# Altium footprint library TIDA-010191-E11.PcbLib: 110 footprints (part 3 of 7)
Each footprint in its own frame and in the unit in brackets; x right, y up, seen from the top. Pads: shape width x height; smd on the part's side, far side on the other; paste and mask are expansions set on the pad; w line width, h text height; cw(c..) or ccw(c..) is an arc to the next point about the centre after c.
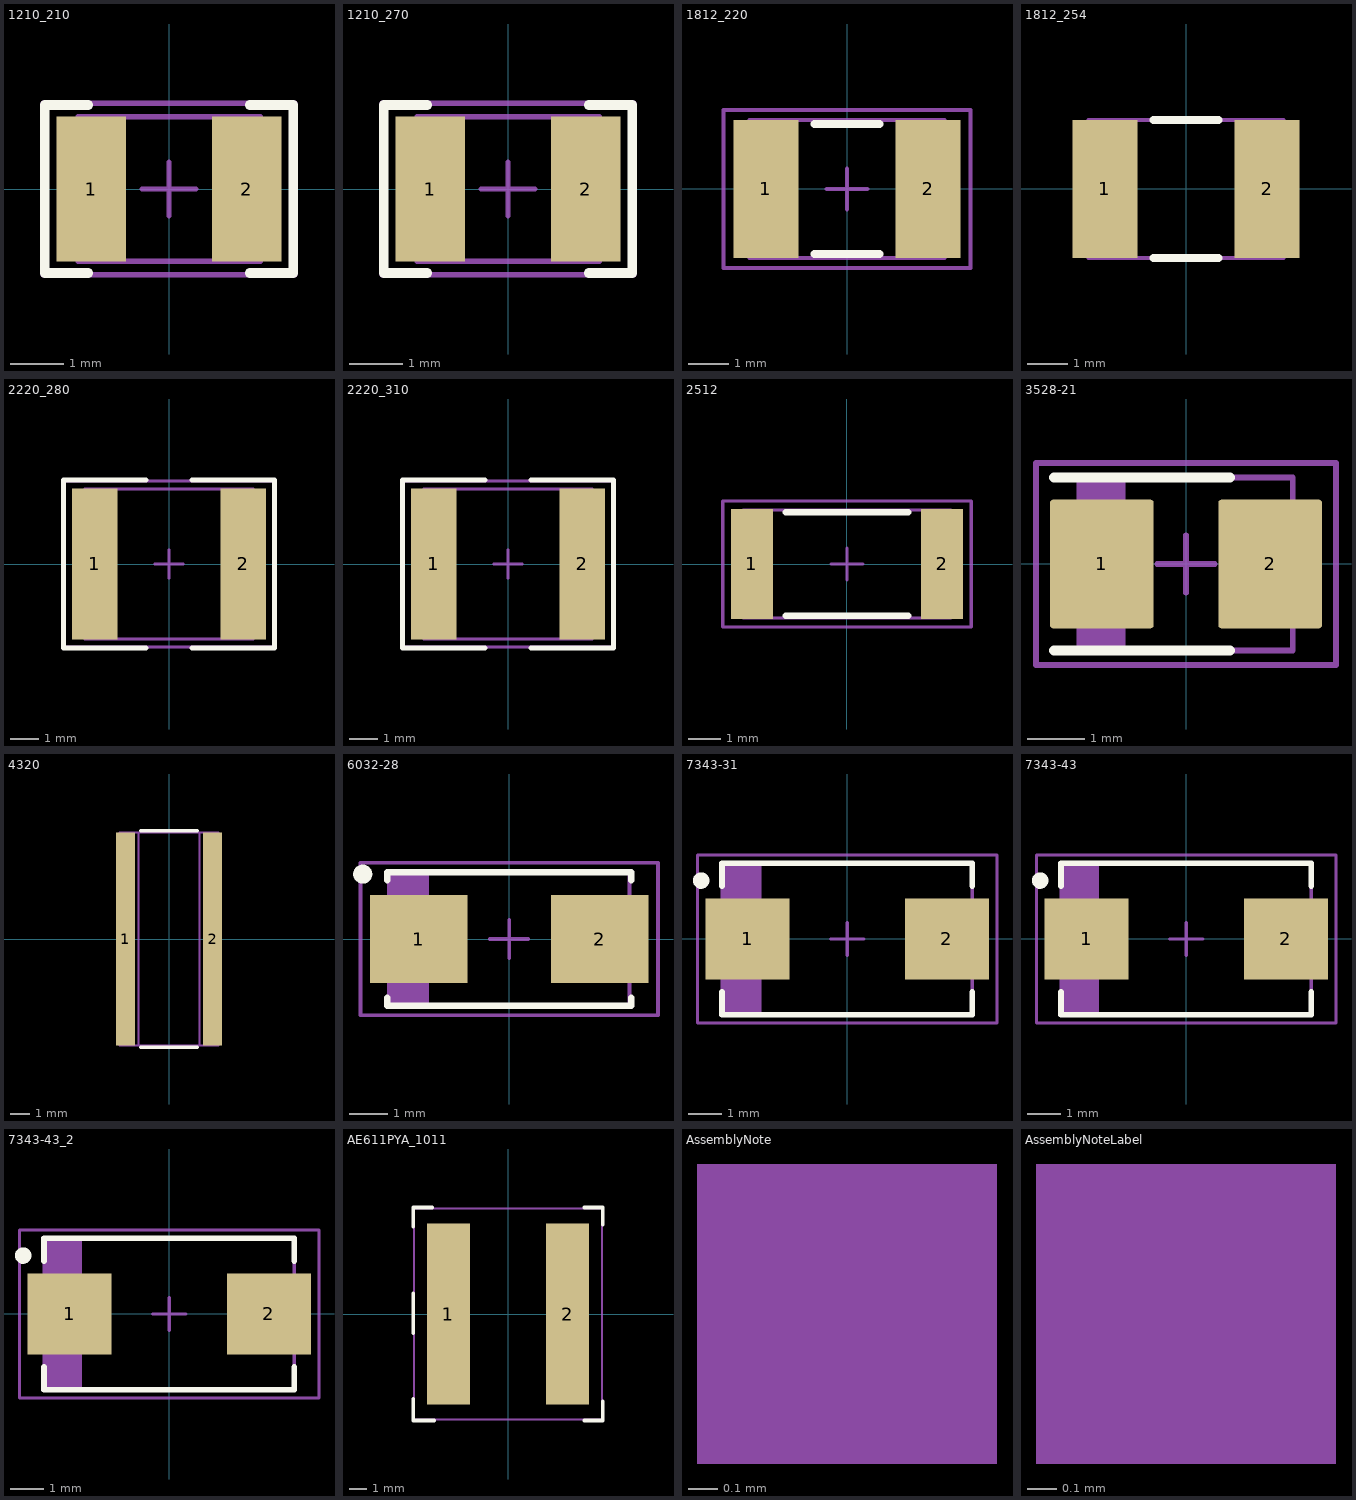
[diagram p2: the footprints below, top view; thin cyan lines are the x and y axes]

## 1210_210 [mm] "1210"
height 2.1
pads (2):
  rect 1.3x2.7 smd: 1(-1.45,0) 2(1.45,0)
Top Overlay:
  lines w0.178: -1.511,-1.568 -2.316,-1.568 -2.316,1.568 -1.511,1.568 ; 1.511,-1.568 2.316,-1.568 2.316,1.568 1.511,1.568
Mechanical 5:
  lines w0.1: -1.7,-1.35 -1.7,1.35 1.7,1.35 1.7,-1.35 -1.7,-1.35
  text ".Designator" at -1.4,-0.375 h0.76
Mechanical 13:
  lines w0.1: -1.2,-1.35 -1.2,1.35 ; 1.2,-1.35 1.2,1.35 ; -1.7,-1.35 1.7,-1.35 1.7,1.35 -1.7,1.35 -1.7,-1.35
Mechanical 15:
  lines w0.1: -0.5,0 0.5,0 ; 0,-0.5 0,0.5 ; -2.35,-1.6 2.35,-1.6 2.35,1.6 -2.35,1.6 -2.35,-1.6
3D body: height 2.1, standoff 0, extent 1.201,-1.349 1.699,1.349
3D body: height 2.1, standoff 0, extent -1.199,-1.349 1.199,1.349
3D body: height 2.1, standoff 0, extent -1.699,-1.349 -1.201,1.349

## 1210_270 [mm] "1210"
height 2.7
pads (2):
  rect 1.3x2.7 smd: 1(-1.45,0) 2(1.45,0)
Top Overlay:
  lines w0.178: -1.511,-1.568 -2.316,-1.568 -2.316,1.568 -1.511,1.568 ; 1.511,-1.568 2.316,-1.568 2.316,1.568 1.511,1.568
Mechanical 5:
  lines w0.1: -1.7,-1.35 1.7,-1.35 1.7,1.35 -1.7,1.35 -1.7,-1.35
  text ".Designator" at -1.4,-0.375 h0.76
Mechanical 13:
  lines w0.1: -1.2,-1.35 -1.2,1.35 ; 1.2,-1.35 1.2,1.35 ; -1.7,-1.35 -1.7,1.35 1.7,1.35 1.7,-1.35 -1.7,-1.35
Mechanical 15:
  lines w0.1: -0.5,0 0.5,0 ; 0,-0.5 0,0.5 ; -2.35,-1.6 -2.35,1.6 2.35,1.6 2.35,-1.6 -2.35,-1.6
3D body: height 2.7, standoff 0, extent -1.699,-1.349 -1.201,1.349
3D body: height 2.7, standoff 0, extent -1.199,-1.349 1.199,1.349
3D body: height 2.7, standoff 0, extent 1.201,-1.349 1.699,1.349

## 1812_220 [mm] "1812"
height 2.2
pads (2):
  rect 1.6x3.4 smd: 1(-2,0) 2(2,0)
Top Overlay:
  lines w0.2: -0.8,-1.6 0.8,-1.6 ; -0.8,1.6 0.8,1.6
Mechanical 5:
  lines w0.1: -2.4,-1.7 -2.4,1.7 2.4,1.7 2.4,-1.7 -2.4,-1.7
  text ".Designator" at -1.875,-0.5 h1.02
Mechanical 13:
  lines w0.1: -1.9,-1.7 -1.9,1.7 ; 1.9,-1.7 1.9,1.7 ; -2.4,-1.7 2.4,-1.7 2.4,1.7 -2.4,1.7 -2.4,-1.7
Mechanical 15:
  lines w0.1: -0.5,0 0.5,0 ; 0,-0.5 0,0.5 ; -3.05,-1.95 3.05,-1.95 3.05,1.95 -3.05,1.95 -3.05,-1.95
3D body: height 2.2, standoff 0, extent 1.901,-1.699 2.399,1.699
3D body: height 2.2, standoff 0, extent -1.899,-1.699 1.899,1.699
3D body: height 2.2, standoff 0, extent -2.399,-1.699 -1.901,1.699

## 1812_254 [mm] "SMD, 2-Leads, Body 4.8x3.4mm"
height 2.54
pads (2):
  rect 1.6x3.4 smd: 1(-2,0) 2(2,0)
Top Overlay:
  lines w0.2: -0.8,-1.7 0.8,-1.7 ; -0.8,1.7 0.8,1.7
Mechanical 5:
  lines w0.1: -1.9,-1.7 -1.9,1.7 ; 1.9,-1.7 1.9,1.7 ; -2.4,-1.7 2.4,-1.7 2.4,1.7 -2.4,1.7 -2.4,-1.7
  text ".Designator" at -1.875,-0.5 h1.02
3D body: height 2.54, standoff 0, extent -2.399,-1.699 -1.901,1.699
3D body: height 2.54, standoff 0, extent -1.899,-1.699 1.899,1.699
3D body: height 2.54, standoff 0, extent 1.901,-1.699 2.399,1.699

## 2220_280 [mm] "Chip Capacitor, Body 5.7x5.0mm, IPC Medium Density"
height 2.8
pads (2):
  rect 1.6x5.3 smd: 1(-2.6,0) 2(2.6,0)
Top Overlay:
  lines w0.178: -0.811,-2.939 -3.693,-2.939 -3.693,2.939 -0.811,2.939 ; 0.811,-2.939 3.693,-2.939 3.693,2.939 0.811,2.939
Mechanical 5:
  lines w0.1: -2.95,-2.625 -2.95,2.625 2.95,2.625 2.95,-2.625 -2.95,-2.625
  text ".Designator" at -1.875,-0.5 h1.02
Mechanical 13:
  lines w0.1: -2.75,-2.625 -2.75,2.625 ; 2.75,-2.625 2.75,2.625 ; -2.95,-2.625 2.95,-2.625 2.95,2.625 -2.95,2.625 -2.95,-2.625
Mechanical 15:
  lines w0.1: -0.5,0 0.5,0 ; 0,-0.5 0,0.5 ; -3.65,-2.9 3.65,-2.9 3.65,2.9 -3.65,2.9 -3.65,-2.9
3D body: height 2.8, standoff 0, extent 2.751,-2.624 2.949,2.624
3D body: height 2.8, standoff 0, extent -2.749,-2.624 2.749,2.624
3D body: height 2.8, standoff 0, extent -2.949,-2.624 -2.751,2.624

## 2220_310 [mm] "2220"
height 3.1
pads (2):
  rect 1.6x5.3 smd: 1(-2.6,0) 2(2.6,0)
Top Overlay:
  lines w0.178: -0.811,-2.939 -3.693,-2.939 -3.693,2.939 -0.811,2.939 ; 0.811,-2.939 3.693,-2.939 3.693,2.939 0.811,2.939
Mechanical 5:
  lines w0.1: -2.95,-2.625 -2.95,2.625 2.95,2.625 2.95,-2.625 -2.95,-2.625
  text ".Designator" at -1.875,-0.5 h1.02
Mechanical 13:
  lines w0.1: -2.75,-2.625 -2.75,2.625 ; 2.75,-2.625 2.75,2.625 ; -2.95,-2.625 2.95,-2.625 2.95,2.625 -2.95,2.625 -2.95,-2.625
Mechanical 15:
  lines w0.1: -0.5,0 0.5,0 ; 0,-0.5 0,0.5 ; -3.65,-2.9 3.65,-2.9 3.65,2.9 -3.65,2.9 -3.65,-2.9
3D body: height 3.1, standoff 0, extent 2.751,-2.624 2.949,2.624
3D body: height 3.1, standoff 0, extent -2.749,-2.624 2.749,2.624
3D body: height 3.1, standoff 0, extent -2.949,-2.624 -2.751,2.624

## 2512 [mm] "Chip Resistor, Body 6.3x3.2mm, IPC Medium Density"
height 0.71
pads (2):
  rect 1.3x3.4 smd: 1(-2.95,0) 2(2.95,0)
Top Overlay:
  lines w0.2: -1.9,-1.6 1.9,-1.6 ; -1.9,1.6 1.9,1.6
Mechanical 5:
  lines w0.1: -3.225,-1.675 3.225,-1.675 3.225,1.675 -3.225,1.675 -3.225,-1.675
  text ".Designator" at -1.85,-0.5 h1.02
Mechanical 13:
  lines w0.1: -2.463,-1.675 -2.463,1.675 ; 2.463,-1.675 2.463,1.675 ; -3.225,-1.675 3.225,-1.675 3.225,1.675 -3.225,1.675 -3.225,-1.675
Mechanical 15:
  lines w0.1: -0.5,0 0.5,0 ; 0,-0.5 0,0.5 ; -3.85,-1.95 3.85,-1.95 3.85,1.95 -3.85,1.95 -3.85,-1.95
3D body: height 0.71, standoff 0, extent -3.224,-1.674 -2.464,1.674
3D body: height 0.71, standoff 0, extent -2.462,-1.674 2.462,1.674
3D body: height 0.71, standoff 0, extent 2.464,-1.674 3.224,1.674

## 3528-21 [mm] "Medium Density IPC, based on Kemet datasheet 2016-10-20"
height 2.1
pads (2):
  rrect6% 1.8x2.23 smd: 1(-1.46,0) 2(1.46,0)
Top Overlay:
  lines w0.178: -2.286,-1.5 0.762,-1.5 ; -2.286,1.5 0.762,1.5
Mechanical 5:
  rectangle: -1.85,-1.5 -1.1,1.5
  lines w0.1: -1.1,-1.5 -1.1,1.5 ; -1.85,-1.5 1.85,-1.5 1.85,1.5 -1.85,1.5 -1.85,-1.5
  text ".Designator" at -0.9,-0.4 h1.2
Mechanical 15:
  lines w0.1: -0.5,0 0.5,0 ; 0,-0.5 0,0.5 ; -2.6,-1.75 -2.6,1.75 2.6,1.75 2.6,-1.75 -2.6,-1.75
3D body "3528-21.stp": height 2.12, standoff 0.01, extent -1.85,-1.5 1.85,1.5

## 4320 [mm] "SUSUMU"
height 0.7
pads (2):
  rect 1x11.2 smd: 1(-2.3,0) 2(2.3,0)
Top Overlay:
  lines w0.18: -1.5,-5.7 1.5,-5.7 ; -1.5,5.7 1.5,5.7
Mechanical 5:
  lines w0.1: -1.6,-5.6 -1.6,5.6 ; 1.6,-5.6 1.6,5.6 ; -2.6,-5.6 -2.6,5.6 2.6,5.6 2.6,-5.6 -2.6,-5.6
  text ".Designator" at 0.5,-1.9 h1.02
3D body: height 0.7, standoff 0, extent -1.599,-5.599 1.599,5.599
3D body: height 0.7, standoff 0, extent 1.601,-5.599 2.599,5.599
3D body: height 0.7, standoff 0, extent -2.599,-5.599 -1.601,5.599

## 6032-28 [mm] "Medium Density IPC based on Vishay Sprague 293D datasheet."
height 2.8
pads (2):
  rect 2.55x2.3 smd: 1(-2.375,0) 2(2.375,0)
Top Overlay:
  circle w0.25: c-3.839,1.7 r0.125
  lines w0.178: -3.2,-1.539 -3.2,-1.75 3.2,-1.75 3.2,-1.539 ; -3.2,1.539 -3.2,1.75 3.2,1.75 3.2,1.539
Mechanical 5:
  rectangle: -3.15,-1.75 -2.15,1.75
  lines w0.1: -2.15,-1.75 -2.15,1.75 ; -3.15,-1.75 3.15,-1.75 3.15,1.75 -3.15,1.75 -3.15,-1.75
  text ".Designator" at -1.85,-0.525 h1.02
Mechanical 15:
  lines w0.1: -0.5,0 0.5,0 ; 0,-0.5 0,0.5 ; -3.9,-2 -3.9,2 3.9,2 3.9,-2 -3.9,-2
3D body: height 2.8, standoff 2.8, extent -3.149,-1.749 -2.151,1.749
3D body: height 2.8, standoff 0, extent -3.15,-1.75 3.15,1.75

## 7343-31 [mm] "Medium Density based on Kemet T495 dimensions"
height 3.1
pads (2):
  rect 2.55x2.45 smd: 1(-3.025,0) 2(3.025,0)
Top Overlay:
  circle w0.25: c-4.439,1.775 r0.125
  lines w0.178: -3.8,-1.614 -3.8,-2.3 3.8,-2.3 3.8,-1.614 ; -3.8,1.614 -3.8,2.3 3.8,2.3 3.8,1.614
Mechanical 5:
  rectangle: -3.8,-2.3 -2.65,2.3
  lines w0.1: -2.65,-2.3 -2.65,2.3 ; -3.8,-2.3 -3.8,2.3 3.8,2.3 3.8,-2.3 -3.8,-2.3
  text ".Designator" at -1.775,-0.5 h1.02
Mechanical 15:
  lines w0.1: -0.5,0 0.5,0 ; 0,-0.5 0,0.5 ; -4.55,-2.55 4.55,-2.55 4.55,2.55 -4.55,2.55 -4.55,-2.55
3D body: height 3.1, standoff 3.1, extent -3.799,-2.299 -2.651,2.299
3D body: height 3.1, standoff 0, extent -3.8,-2.3 3.8,2.3

## 7343-43 [mm] "Medium density IPC based on Kemet T495 series"
height 4.3
pads (2):
  rect 2.55x2.45 smd: 1(-3.025,0) 2(3.025,0)
Top Overlay:
  circle w0.25: c-4.439,1.775 r0.125
  lines w0.178: -3.8,-1.614 -3.8,-2.3 3.8,-2.3 3.8,-1.614 ; -3.8,1.614 -3.8,2.3 3.8,2.3 3.8,1.614
Mechanical 5:
  rectangle: -3.8,-2.3 -2.7,2.3
  lines w0.1: -2.7,-2.3 -2.7,2.3 ; -3.8,-2.3 3.8,-2.3 3.8,2.3 -3.8,2.3 -3.8,-2.3
  text ".Designator" at -1.524,-0.508 h1.02
Mechanical 15:
  lines w0.1: -0.5,0 0.5,0 ; 0,-0.5 0,0.5 ; -4.55,-2.55 4.55,-2.55 4.55,2.55 -4.55,2.55 -4.55,-2.55
3D body: height 4.3, standoff 0, extent -3.8,-2.3 3.8,2.3
3D body: height 4.3, standoff 4.3, extent -3.799,-2.299 -2.701,2.299

## 7343-43_2 [mm]
pads (2):
  rect 2.55x2.45 smd: 1(-3.025,0) 2(3.025,0)
Top Overlay:
  circle w0.25: c-4.439,1.775 r0.125
  lines w0.178: -3.8,-1.614 -3.8,-2.3 3.8,-2.3 3.8,-1.614 ; -3.8,1.614 -3.8,2.3 3.8,2.3 3.8,1.614
Mechanical 5:
  rectangle: -3.8,-2.3 -2.7,2.3
  lines w0.1: -2.7,-2.3 -2.7,2.3 ; -3.8,-2.3 -3.8,2.3 3.8,2.3 3.8,-2.3 -3.8,-2.3
  text ".Designator" at -1.524,-0.508 h1.02
Mechanical 15:
  lines w0.1: -0.5,0 0.5,0 ; 0,-0.5 0,0.5 ; -4.55,-2.55 -4.55,2.55 4.55,2.55 4.55,-2.55 -4.55,-2.55
3D body: height 4.3, standoff 4.3, extent -3.799,-2.299 -2.701,2.299
3D body: height 4.3, standoff 0, extent -3.8,-2.3 3.8,2.3

## AE611PYA_1011 [mm] "Coilcraft"
height 10
pads (2):
  rect 2.38x10.11 smd: 1(-3.325,0) 2(3.325,0)
Top Overlay:
  lines w0.2: -5.3,-4.75 -5.3,-5.95 -4.125,-5.95 ; -5.3,-1.075 -5.3,1.15 ; -5.3,4.875 -5.3,5.95 -4.225,5.95 ; 4.25,-5.95 5.3,-5.95 5.3,-4.875 ; 4.25,5.95 5.3,5.95 5.3,5
Mechanical 5:
  circle w0.1: c-3.3,0 r0.51
  lines w0.1: -5.25,-5.9 5.25,-5.9 5.25,5.9 -5.25,5.9 -5.25,-5.9
  text ".Designator" at -1.8,-0.7 h1.85
3D body: height 10, standoff 0, extent -5.249,-5.899 5.249,5.899
3D body: height 10.05, standoff 5, extent -3.809,-0.509 -2.791,0.509

## AssemblyNote [mm] "Assembly Note"
Mechanical 5:
  rectangle: 15.9,83.109 16.916,84.125
  text ".Designator" at 12.065,83.033 h0.64
  text ".Comment" at 17.475,83.16 h0.64

## AssemblyNoteLabel [mm] "Assembly Note for PCB Labels"
Mechanical 5:
  rectangle: 15.799,83.744 16.815,84.76
  text "Install label in silkscreened box after final wash.  Text shall be 8 pt font.  Text shall be per the Label Table in the PDF schematic." at 17.755,83.896 h0.64
  text ".Designator" at 11.913,83.845 h0.64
